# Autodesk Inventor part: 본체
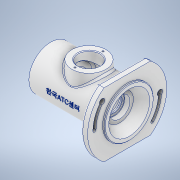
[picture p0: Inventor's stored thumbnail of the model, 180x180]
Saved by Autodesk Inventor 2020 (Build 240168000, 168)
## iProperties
Created: 2022-05
Part Number: 본체
Material: 알루미늄 6061
Document SubType Name: Modeling
Designer: Student
Density: 2.7 g/cm^3
Appearance: 알루미늄 - 평지
Mass: 692.617 g
Surface Area: 620.9 cm^2
Volume: 256.525 cm^3
Author: Student
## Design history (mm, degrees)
sketch "스케치3"
  geometry: L1 (47, 33.985)-(47, -33.985); L2 (-47, 33.985)-(-47, -33.985); A1 r 58 centre (0, 0) between (47, 33.985) and (-47, 33.985); A2 r 58 centre (0, 0) between (-47, -33.985) and (47, -33.985); 1 further point
  constraints: 4 end point, 4 point on circle, 2 centre point, 1 coincident, 1 parallel, 1 vertical
  dimensions: "d1" = 94 distance between parallel lines of L2 L1; "d2" = 47 horizontal distance of L1.start point (0, 0); "d3" = 58 radius of A2; "d4" = 58 radius of A1
extrude "돌출1" new body sketch "스케치3" distance "d5" = 10; taper "d6" = 0 deg
sketch "스케치4"
  geometry: C1 r 32 at (0, 0); 1 further point
  constraints: 1 centre point, 1 coincident
  dimensions: "d7" = 32 radius of C1
extrude "돌출2" join sketch "스케치4" distance "d8" = 102; taper "d9" = 0 deg
sketch "스케치6"
  geometry: C1 r 36 at (0, 0); 1 further point
  constraints: 1 centre point, 1 coincident
  dimensions: "d25" = 72 diameter of C1
extrude "돌출3" join sketch "스케치6" distance "d26" = 3; taper "d27" = 0 deg
sketch "스케치7"
  geometry: L1 (-118.309, 0)-(16.901, 0); L2 (0, -47)-(-10, -47) reference; L3 (-104, 0)-(-104, 24); L4 (-104, 24)-(-101, 24); L5 (-101, 24)-(-101, 22.5); L6 (-101, 22.5)-(-90, 22.5); L7 (-90, 22.5)-(-90, 17.5); L8 (-90, 17.5)-(-88.25, 17.5); L9 (-88.25, 17.5)-(-88.25, 18.5); L10 (-88.25, 18.5)-(-86, 18.5); L11 (-86, 18.5)-(-86, 17.5); L12 (-86, 17.5)-(-75, 17.5); L13 (-75, 17.5)-(-75, 27); L14 (-75, 27)-(-37, 27); L15 (3, -36)-(3, 36) reference; L16 (-26, 15)-(-21, 15); L17 (-21, 15)-(-21, 11); L18 (-21, 11)-(-19, 11); L19 (-19, 11)-(-19, 15); L20 (-11, 20)-(3, 30); L21 (-37, 27)-(-37, 17.5); L22 (-37, 17.5)-(-26, 17.5); L23 (-26, 17.5)-(-26, 15); L24 (-19, 15)-(-11.7, 15); L25 (-11.7, 15)-(-11, 15); L26 (-11, 15)-(-11, 20); 2 further points
  constraints: 48 end point, 14 perpendicular, 4 horizontal, 4 point on line, 3 vertical
  dimensions: "d28" = 47 distance between parallel lines of L2 L1; "d29" = 3 distance of L3.end L4.end; "d30" = 11 distance of L5.end L6.end; "d31" = 48 diameter of L4 L1; "d32" = 45 diameter of L6 L1; "d33" = 35 diameter of L8 L1; "d34" = 4 horizontal distance of L10.end L7.end; "d35" = 1.75 distance of L7.end L8.end; "d36" = 11 distance of L11.end L12.end; "d37" = 54 diameter of L14 L1; "d38" = 38 distance of L13.end L14.end; "d40" = 11 distance of L21.end L22.end; "d41" = 35 diameter of L22 L1; "d42" = 5 distance of L16.start L16.end; "d46" = 7.3 distance of L19.end L24.end; "d47" = 2 distance of L17.end L18.end; "d48" = 30 diameter of L24 L1; "d49" = 60 diameter of L20.end L1; "d50" = 40 diameter of L20.start L1; "d51" = 22 diameter of L18 L1; "d52" = 30 diameter of L16 L1; "d53" = 0.7 distance of L24.end L25.end; "d54" = 14 horizontal distance of L20.end L20.start; "d55" = 37 diameter of L10 L1
revolve "회전1" sketch "스케치7" stored, may be unused: angle "d56" = 90 deg
fillet "모깎기1" dims "d57" = 3
fillet "모깎기2" dims "d58" = 0.6, "d59" = 0.5
chamfer "모따기1" distance "d60" = 0.7; stored, may be unused: second distance "d61" = 2, angle "d62" = 30 deg
chamfer "모따기2" distance "d63" = 1; stored, may be unused: second distance "d64" = 2, angle "d65" = 45 deg
sketch "스케치8"
  geometry: C1 r 32 at (0, 0) reference; 1 further point
hole "구멍1" sketch "스케치8" at (0, 0) diameter "d66" = 43.376; stored, may be unused: countersink angle "d70" = 90 deg, drill point angle "d72" = 0 deg; dims "d67" = 8, "d68" = 4, "d69" = 2, "d71" = 8
node "작업 평면1"
sketch "스케치9"
  geometry: L1 (112, -32)-(112, 32) reference; L2 (112, 0)-(56, 0); C1 r 25 at (56, 0); C2 r 16 at (56, 0); 1 further point
  constraints: 2 centre point, 2 end point, 1 coincident, 1 horizontal, 1 midpoint
  dimensions: "d74" = 25 radius of C1; "d75" = 16 radius of C2; "d76" = 56 distance from line of L1 C1.centre
extrude "돌출4" join sketch "스케치9" stored distance "d77" = 3; taper "d78" = 0 deg
extrude "돌출5" cut sketch "스케치9" stored distance "d79" = 3; taper "d80" = 0 deg
feature "면 기울기1" dims angle "d81" = 5 deg
chamfer "모따기3" distance "d82" = 1; stored, may be unused: second distance "d83" = 2, angle "d84" = 45 deg
fillet "모깎기3" dims "d85" = 3
chamfer "모따기4" distance "d86" = 1; stored, may be unused: second distance "d87" = 2, angle "d88" = 45 deg
sketch "스케치10"
  geometry: L1 (0, 0)-(-48, 0); L2 (0, 0)-(-36.77, -30.854); L3 (36.77, 30.854)-(0, 0); L4 (0, 0)-(48, 0); A1 r 48 centre (0, 0) between (48, 0) and (36.77, 30.854); A2 r 52 centre (0, 0) between (52, 0) and (39.834, 33.425); A3 r 44 centre (0, 0) between (44, 0) and (33.706, 28.283); A4 r 4 centre (48, 0) between (44, 0) and (52, 0); A5 r 4 centre (36.77, 30.854) between (39.834, 33.425) and (33.706, 28.283); A6 r 48 centre (0, 0) between (-48, 0) and (-36.77, -30.854); A7 r 52 centre (0, 0) between (-52, 0) and (-39.834, -33.425); A8 r 44 centre (0, 0) between (-44, 0) and (-33.706, -28.283); A9 r 4 centre (-48, 0) between (-44, 0) and (-52, 0); A10 r 4 centre (-36.77, -30.854) between (-39.834, -33.425) and (-33.706, -28.283); A11 r 4 centre (36.77, 30.854) between (37.033, 26.862) and (40.58, 29.636); A12 r 4 centre (-48, 0) between (-45.636, -3.227) and (-50.136, -3.382); A13 r 48 centre (0, 0) between (48, 0) and (36.77, 30.854); A14 r 50.25 centre (0, 0) between (50.25, 0) and (40.58, 29.636); A15 r 45.75 centre (0, 0) between (45.75, 0) and (37.033, 26.862); A16 r 2.25 centre (48, 0) between (45.75, 0) and (50.25, 0); A17 r 48 centre (0, 0) between (-48, 0) and (-36.77, -30.854); A18 r 50.25 centre (0, 0) between (-50.136, -3.382) and (-38.494, -32.3); A19 r 45.75 centre (0, 0) between (-45.636, -3.227) and (-35.047, -29.408); A20 r 2.25 centre (-36.77, -30.854) between (-38.494, -32.3) and (-35.047, -29.408); 8 further points
  constraints: 41 point on circle, 20 centre point, 12 tangent, 8 end point, 6 coincident, 2 horizontal, 1 concentric, 1 other
  dimensions: "d95" = 48 radius of A6; "d96" = 4 radius of A4; "d99" = 40 deg angle of L2 L1; "d101" = 48 distance of L4.end L1.start; "d102" = 40 deg angle of L4 L3; "d103" = 4 radius of A11; "d104" = 4 radius of A12; "d126" = 2.25 radius of A16; "d127" = 2.25 radius of A20
extrude "돌출6" cut sketch "스케치10" distance "d105" = 4.4; taper "d106" = 0 deg
extrude "돌출7" cut sketch "스케치10" stored distance "d107" = 4.4; taper "d108" = 0 deg
extrude "돌출8" cut sketch "스케치10" extent not by distance; stored distance "d128" = 0; taper "d129" = 0 deg
sketch "스케치14"
  geometry: L1 (-112, 32)-(-112, -32) reference; C1 r 17 at (-56, 0) reference; 2 further points
  dimensions: "d131" = 56 distance from line of L1 point (-56, 20.5); "d132" = 20.5 distance of C1.centre point (-56, 20.5)
hole "구멍2" sketch "스케치14" at (-56, 20.5) diameter "d133" = 2.459; stored, may be unused: countersink angle "d137" = 90 deg, drill point angle "d139" = 118 deg; dims "d134" = 6, "d135" = 4, "d136" = 2, "d138" = 8
node "작업 평면2"
sketch "스케치15"
  geometry: L1 (0, -47)-(0, 47) reference; 3 further points
  constraints: 1 horizontal alignment, 1 midpoint, 1 other
  dimensions: "d144" = 62 distance from line of L1 point (-62, 0)
feature "엠보싱1" sketch "스케치15" dims "d1" = 94, "d2" = 47, "d3" = 58, "d4" = 58, "d145" = 0.5, "d146" = 0
node "솔리드1"
pattern_circular "원형 패턴1" dims angle "d141" = 360 deg
feature "A9D066F2-1C7D-4E18-AEED-F7BC21143FA4" dims "d66" = 43.376, "d67" = 8, "d68" = 4, "d69" = 2, "d70" = 90 deg, "d71" = 8, "d72" = 0
other parameters: "d0" = 116, "d73" = 38, "d143" = 57.5
